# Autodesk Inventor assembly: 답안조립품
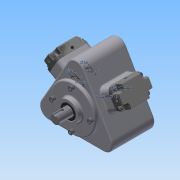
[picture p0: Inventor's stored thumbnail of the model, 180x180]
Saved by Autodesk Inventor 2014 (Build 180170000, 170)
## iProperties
Created: 2015-06
Part Number: 답안조립품
Document SubType Name: Assembly
Designer: Administrator
Mass: 4476.7 g
Surface Area: 2414.93 cm^2
Volume: 1564.62 cm^3
Density: 2.86121 g/cm^3
Author: Administrator
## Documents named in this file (20)
- C:\Documents and Settings\MYHOME\바탕 화면\350605V1039\답안조립품.iam
- C:\Documents and Settings\MYHOME\바탕 화면\350605V1039\본체.ipt
- C:\Documents and Settings\MYHOME\바탕 화면\350605V1039\앞커버.ipt
- C:\Documents and Settings\MYHOME\바탕 화면\350605V1039\베어링 NA 4904.ipt
- 베어링 NA 4904.ipt
- C:\Documents and Settings\MYHOME\바탕 화면\350605V1039\오일실.ipt
- 오일실.ipt
- C:\Documents and Settings\MYHOME\바탕 화면\350605V1039\M6x0.7x20.ipt
- M6x0.7x20.ipt
- C:\Documents and Settings\MYHOME\바탕 화면\350605V1039\편심축.ipt
- C:\Documents and Settings\MYHOME\바탕 화면\350605V1039\헤더커버.ipt
- 헤더커버.ipt
- C:\Documents and Settings\MYHOME\바탕 화면\350605V1039\M4x0.5x16.ipt
- M4x0.5x16.ipt
- C:\Documents and Settings\MYHOME\바탕 화면\350605V1039\부시.ipt
- C:\Documents and Settings\MYHOME\바탕 화면\350605V1039\슬라이드.ipt
- C:\Documents and Settings\MYHOME\바탕 화면\350605V1039\8-스프링.ipt
- C:\Documents and Settings\MYHOME\바탕 화면\350605V1039\11-스프링.ipt
- C:\Documents and Settings\MYHOME\바탕 화면\350605V1039\9-스프링.ipt
- C:\Documents and Settings\MYHOME\바탕 화면\350605V1039\10-스프링.ipt
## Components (18 placed, 7 different names)
1. 헤더커버:1
2. 헤더커버:2
3. M4x0.5x16:1
4. M4x0.5x16:2
5. M4x0.5x16:3
6. M4x0.5x16:4
7. M4x0.5x16:5
8. M4x0.5x16:6
9. M4x0.5x16:7
10. M4x0.5x16:8
11. 8-스프링:1
12. 11-스프링:1
13. 9-스프링:1
14. 10-스프링:1
15. M6x0.7x20:1
16. M6x0.7x20:2
17. M6x0.7x20:3
18. M6x0.7x20:4
